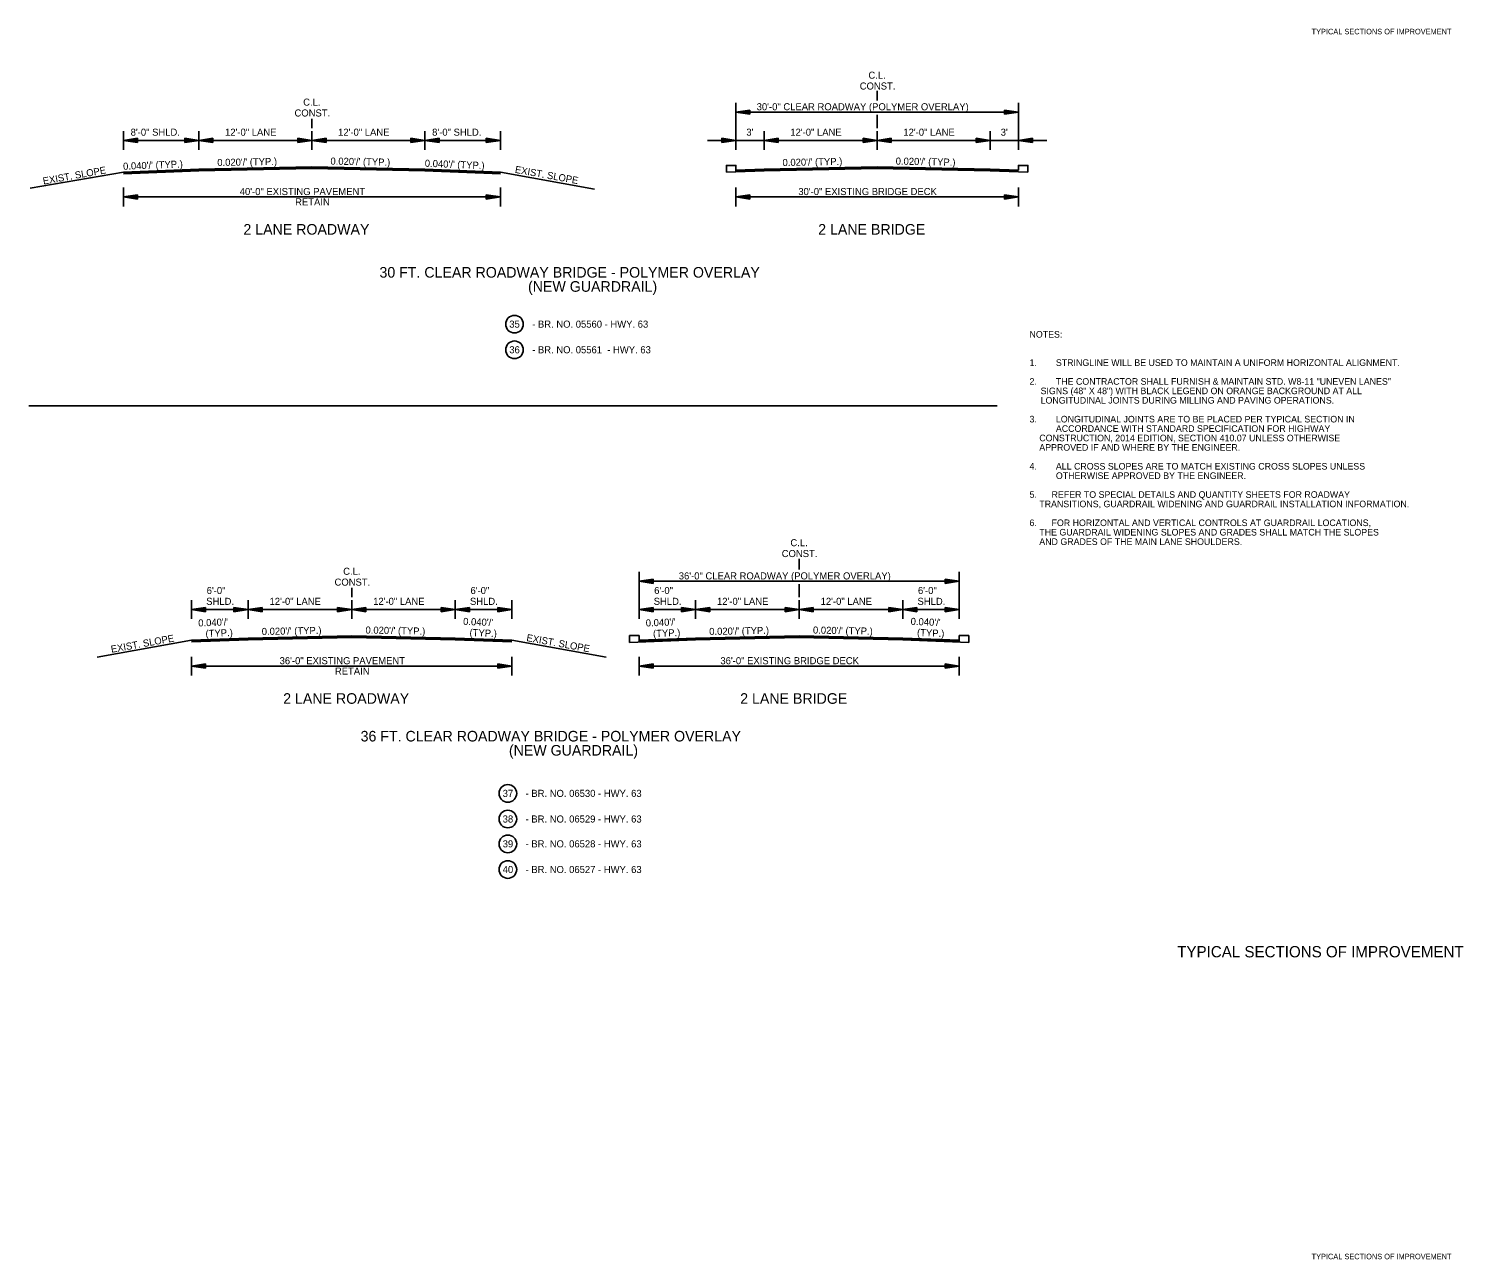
# Model space of a CAD drawing. Extents: x 545241 to 1930787, y -1971772 to 596640.
# Drawn here: x 546745 to 548268, y -1965592 to -1964286 of the extents above; entities that cross this region are included whole.
import ezdxf

# ---------------------------------------------------------------- set-up
doc = ezdxf.new("R2010")
doc.units = 0
for name, color, linetype in [('R_Border', 7, 'Continuous'), ('R_Border Notes', 7, 'Continuous'), ('R_Border Prem', 7, 'Continuous'), ('R_Draft', 7, 'Continuous')]:
    doc.layers.add(name, color=color, linetype=linetype)

# ---------------------------------------------------------------- blocks, each defined once
blk = doc.blocks.new('ARROW')
at = {"layer": 'R_Draft'}
for p, q in [((-2, 0.3), (0, 0)), ((-2, 0.3), (-2, -0.3)), ((-2, 0.25), (-0.334, 0)), ((-2, 0.199), (-0.678, 0)), ((-2, 0.149), (-1.011, 0)), ((-2, 0.097), (-1.35, 0)), ((-2, 0.047), (-1.684, 0)), ((-2, -0.3), (0, 0)), ((-2, -0.098), (-1.35, 0)), ((-2, -0.199), (-0.678, 0)), ((-2, -0.25), (-0.334, 0)), ((-2, -0.149), (-1.011, 0)), ((-2, -0.047), (-1.684, 0))]:
    blk.add_line(p, q, dxfattribs=at)

msp = doc.modelspace()

# ---------------------------------------------------------------- linework, layer by layer
at = {"layer": 'R_Border'}
for p, q in [((547645.7, -1964352.1), (547645.7, -1964362.1)), ((547495.7, -1964364.6), (547495.7, -1964414.6)), ((547795.7, -1964364.6), (547795.7, -1964414.6)), ((547045.7, -1964381.6), (547045.7, -1964391.6)), ((547495.7, -1964374.6), (547795.7, -1964374.6)), ((547645.7, -1964377.6), (547645.7, -1964391.6)), ((546845.7, -1964394.6), (546845.7, -1964414.6)), ((546925.7, -1964394.6), (546925.7, -1964414.6)), ((547045.7, -1964394.6), (547045.7, -1964414.6)), ((547165.7, -1964394.6), (547165.7, -1964414.6)), ((547245.7, -1964394.6), (547245.7, -1964414.6)), ((547525.7, -1964394.6), (547525.7, -1964414.6)), ((547645.7, -1964394.6), (547645.7, -1964414.6)), ((547765.7, -1964394.6), (547765.7, -1964414.6)), ((546845.7, -1964404.6), (547245.7, -1964404.6)), ((547465.7, -1964404.6), (547825.7, -1964404.6)), ((546845.7, -1964438.2), (546746.5, -1964455.3)), ((547245.7, -1964438.2), (547345.7, -1964456.2)), ((546845.7, -1964454.6), (546845.7, -1964474.6)), ((547245.7, -1964454.6), (547245.7, -1964474.6)), ((547495.7, -1964454.6), (547495.7, -1964474.6)), ((547795.7, -1964454.6), (547795.7, -1964474.6)), ((546845.7, -1964464.6), (547245.7, -1964464.6)), ((547495.7, -1964464.6), (547795.7, -1964464.6)), ((546745.1, -1964686.1), (547773, -1964686.1)), ((547562.9, -1964848.8), (547562.9, -1964860)), ((547392.9, -1964862.5), (547392.9, -1964912.5)), ((547392.9, -1964872.5), (547732.9, -1964872.5)), ((547732.9, -1964862.5), (547732.9, -1964912.5)), ((547087.9, -1964879.5), (547087.9, -1964889.5)), ((547562.9, -1964875.5), (547562.9, -1964889.5)), ((546917.9, -1964892.5), (546917.9, -1964912.5)), ((546917.9, -1964902.5), (547257.9, -1964902.5)), ((546977.9, -1964892.5), (546977.9, -1964912.5)), ((547087.9, -1964892.5), (547087.9, -1964912.5)), ((547197.9, -1964892.5), (547197.9, -1964912.5)), ((547257.9, -1964892.5), (547257.9, -1964912.5)), ((547392.9, -1964902.5), (547732.9, -1964902.5)), ((547452.9, -1964892.5), (547452.9, -1964912.5)), ((547562.9, -1964892.5), (547562.9, -1964912.5)), ((547672.9, -1964892.5), (547672.9, -1964912.5)), ((546917.9, -1964935.1), (546817.9, -1964953.1)), ((547257.9, -1964935.1), (547357.9, -1964953.1)), ((546917.9, -1964952.5), (546917.9, -1964972.5)), ((546917.9, -1964962.5), (547257.9, -1964962.5)), ((547257.9, -1964952.5), (547257.9, -1964972.5)), ((547392.9, -1964952.5), (547392.9, -1964972.5)), ((547392.9, -1964962.5), (547732.9, -1964962.5)), ((547732.9, -1964952.5), (547732.9, -1964972.5))]:
    msp.add_line(p, q, dxfattribs=at)
for points in [[(547495.7, -1964437.7), (547495.7, -1964431.2), (547485.7, -1964431.2), (547485.7, -1964438.4)], [(547795.7, -1964436.2), (547795.7, -1964431.2), (547805.7, -1964431.2), (547805.7, -1964438.4)], [(546845.7, -1964438.2), (546925.7, -1964435), (547045.7, -1964432.6), (547165.7, -1964435), (547245.7, -1964438.2)], [(546845.7, -1964438.5), (546925.7, -1964435.3), (547045.7, -1964432.9), (547165.7, -1964435.3), (547245.7, -1964438.5)], [(546845.7, -1964438.8), (546925.7, -1964435.6), (547045.7, -1964433.2), (547165.7, -1964435.6), (547245.7, -1964438.8)], [(546845.7, -1964439.1), (546925.7, -1964435.9), (547045.7, -1964433.5), (547165.7, -1964435.9), (547245.7, -1964439.1)], [(546845.7, -1964439.4), (546925.7, -1964436.2), (547045.7, -1964433.8), (547165.7, -1964436.2), (547245.7, -1964439.4)], [(546845.7, -1964439.7), (546925.7, -1964436.5), (547045.7, -1964434.1), (547165.7, -1964436.5), (547245.7, -1964439.7)], [(546845.7, -1964440), (546925.7, -1964436.8), (547045.7, -1964434.4), (547165.7, -1964436.8), (547245.7, -1964440)], [(547485.7, -1964438.4), (547525.7, -1964436.8), (547645.7, -1964434.4), (547765.7, -1964436.8), (547805.7, -1964438.4)], [(547495.7, -1964436.2), (547525.7, -1964435), (547645.7, -1964432.6), (547765.7, -1964435), (547795.7, -1964436.2)], [(547495.7, -1964436.5), (547525.7, -1964435.3), (547645.7, -1964432.9), (547765.7, -1964435.3), (547795.7, -1964436.5)], [(547495.7, -1964436.8), (547525.7, -1964435.6), (547645.7, -1964433.2), (547765.7, -1964435.6), (547795.7, -1964436.8)], [(547495.7, -1964437.1), (547525.7, -1964435.9), (547645.7, -1964433.5), (547765.7, -1964435.9), (547795.7, -1964437.1)], [(547495.7, -1964437.4), (547525.7, -1964436.2), (547645.7, -1964433.8), (547765.7, -1964436.2), (547795.7, -1964437.4)], [(547495.7, -1964437.7), (547525.7, -1964436.5), (547645.7, -1964434.1), (547765.7, -1964436.5), (547795.7, -1964437.7)], [(546917.9, -1964935.1), (546977.9, -1964932.7), (547087.9, -1964930.5), (547197.9, -1964932.7), (547257.9, -1964935.1)], [(546917.9, -1964935.4), (546977.9, -1964933), (547087.9, -1964930.8), (547197.9, -1964933), (547257.9, -1964935.4)], [(546917.9, -1964935.7), (546977.9, -1964933.3), (547087.9, -1964931.1), (547197.9, -1964933.3), (547257.9, -1964935.7)], [(546917.9, -1964936), (546977.9, -1964933.6), (547087.9, -1964931.4), (547197.9, -1964933.6), (547257.9, -1964936)], [(546917.9, -1964936.3), (546977.9, -1964933.9), (547087.9, -1964931.7), (547197.9, -1964933.9), (547257.9, -1964936.3)], [(546917.9, -1964936.6), (546977.9, -1964934.2), (547087.9, -1964932), (547197.9, -1964934.2), (547257.9, -1964936.6)], [(546917.9, -1964936.9), (546977.9, -1964934.5), (547087.9, -1964932.3), (547197.9, -1964934.5), (547257.9, -1964936.9)], [(547392.9, -1964936.6), (547392.9, -1964930.1), (547382.9, -1964930.1), (547382.9, -1964937.3)], [(547382.9, -1964937.3), (547452.9, -1964934.5), (547562.9, -1964932.3), (547672.9, -1964934.5), (547742.9, -1964937.3)], [(547392.9, -1964935.1), (547452.9, -1964932.7), (547562.9, -1964930.5), (547672.9, -1964932.7), (547732.9, -1964935.1)], [(547392.9, -1964935.4), (547452.9, -1964933), (547562.9, -1964930.8), (547672.9, -1964933), (547732.9, -1964935.4)], [(547392.9, -1964935.7), (547452.9, -1964933.3), (547562.9, -1964931.1), (547672.9, -1964933.3), (547732.9, -1964935.7)], [(547392.9, -1964936), (547452.9, -1964933.6), (547562.9, -1964931.4), (547672.9, -1964933.6), (547732.9, -1964936)], [(547392.9, -1964936.3), (547452.9, -1964933.9), (547562.9, -1964931.7), (547672.9, -1964933.9), (547732.9, -1964936.3)], [(547392.9, -1964936.6), (547452.9, -1964934.2), (547562.9, -1964932), (547672.9, -1964934.2), (547732.9, -1964936.6)], [(547732.9, -1964937.3), (547732.9, -1964930.1), (547742.9, -1964930.1), (547742.9, -1964937.3)]]:
    msp.add_lwpolyline(points, dxfattribs=at)
for centre in [(547260.7, -1964599.6), (547260.7, -1964626.8), (547253.7, -1965097.6), (547253.7, -1965124.8), (547253.7, -1965151.2), (547253.7, -1965178.4)]:
    msp.add_circle(centre, 9.34, dxfattribs=at)

# ---------------------------------------------------------------- block references
at = {"layer": 'R_Border', "xscale": 7.5, "yscale": 7.5, "rotation": 180}
for p in [(547495.7, -1964374.6), (546845.7, -1964404.6), (546925.7, -1964404.6), (547045.7, -1964404.6), (547165.7, -1964404.6), (547525.7, -1964404.6), (547645.7, -1964404.6), (547795.7, -1964404.6), (546845.7, -1964464.6), (547495.7, -1964464.6), (547392.9, -1964872.5), (546917.9, -1964902.5), (546977.9, -1964902.5), (547087.9, -1964902.5), (547197.9, -1964902.5), (547392.9, -1964902.5), (547452.9, -1964902.5), (547562.9, -1964902.5), (547672.9, -1964902.5), (546917.9, -1964962.5), (547392.9, -1964962.5)]:
    msp.add_blockref('ARROW', p, dxfattribs=at)
at = {"layer": 'R_Border', "xscale": 7.5, "yscale": 7.5}
for p in [(547795.7, -1964374.6), (546925.7, -1964404.6), (547045.7, -1964404.6), (547165.7, -1964404.6), (547245.7, -1964404.6), (547495.7, -1964404.6), (547645.7, -1964404.6), (547765.7, -1964404.6), (547245.7, -1964464.6), (547795.7, -1964464.6), (547732.9, -1964872.5), (546977.9, -1964902.5), (547087.9, -1964902.5), (547197.9, -1964902.5), (547257.9, -1964902.5), (547452.9, -1964902.5), (547562.9, -1964902.5), (547672.9, -1964902.5), (547732.9, -1964902.5), (547257.9, -1964962.5), (547732.9, -1964962.5)]:
    msp.add_blockref('ARROW', p, dxfattribs=at)

# ---------------------------------------------------------------- texts
at = {"layer": 'R_Border'}
for s, height, p in [('C.L.', 7.5, (547636.4, -1964339.1)), ('CONST.', 7.5, (547627.2, -1964350.6)), ('C.L.', 7.5, (547036.4, -1964367.7)), ('30\'-0" CLEAR ROADWAY (POLYMER OVERLAY)', 7.5, (547517.8, -1964372.6)), ('CONST.', 7.5, (547027.2, -1964379.2)), ('8\'-0" SHLD.', 7.5, (546853.3, -1964399.6)), ('12\'-0" LANE', 7.5, (546953.5, -1964399.6)), ('12\'-0" LANE', 7.5, (547073.5, -1964399.6)), ('8\'-0" SHLD.', 7.5, (547173.3, -1964399.6)), ("3'", 7.5, (547506.8, -1964399.6)), ('12\'-0" LANE', 7.5, (547553.5, -1964399.6)), ('12\'-0" LANE', 7.5, (547673.5, -1964399.6)), ("3'", 7.5, (547776.8, -1964399.6)), ('40\'-0" EXISTING PAVEMENT', 7.5, (546969.1, -1964462.6)), ('30\'-0" EXISTING BRIDGE DECK', 7.5, (547562, -1964462.6)), ('RETAIN', 7.5, (547027.9, -1964473.6)), ('2 LANE ROADWAY', 11.25, (546973, -1964504.6)), ('2 LANE BRIDGE', 11.25, (547583.1, -1964504.6)), ('30 FT. CLEAR ROADWAY BRIDGE - POLYMER OVERLAY', 11.25, (547117.4, -1964550.2)), ('(NEW GUARDRAIL)', 11.25, (547275.1, -1964565.2)), ('C.L.', 7.5, (547553.6, -1964835.3)), ('CONST.', 7.5, (547544.4, -1964846.8)), ('C.L.', 7.5, (547078.9, -1964865.6)), ('CONST.', 7.5, (547069.7, -1964877.1)), ('36\'-0" CLEAR ROADWAY (POLYMER OVERLAY)', 7.5, (547435.1, -1964870.5)), ('6\'-0"', 7.5, (546934, -1964886)), ('6\'-0"', 7.5, (547214, -1964886)), ('6\'-0"', 7.5, (547409, -1964886)), ('6\'-0"', 7.5, (547689, -1964886)), ('SHLD.', 7.5, (546933.5, -1964897.5)), ('12\'-0" LANE', 7.5, (547000.7, -1964897.5)), ('12\'-0" LANE', 7.5, (547110.7, -1964897.5)), ('SHLD.', 7.5, (547213.5, -1964897.5)), ('SHLD.', 7.5, (547408.5, -1964897.5)), ('12\'-0" LANE', 7.5, (547475.7, -1964897.5)), ('12\'-0" LANE', 7.5, (547585.7, -1964897.5)), ('SHLD.', 7.5, (547688.5, -1964897.5)), ('36\'-0" EXISTING PAVEMENT', 7.5, (547011.4, -1964960.5)), ('RETAIN', 7.5, (547070.1, -1964971.5)), ('36\'-0" EXISTING BRIDGE DECK', 7.5, (547479.3, -1964960.5)), ('2 LANE ROADWAY', 11.25, (547015.2, -1965002.5)), ('2 LANE BRIDGE', 11.25, (547500.3, -1965002.5)), ('36 FT. CLEAR ROADWAY BRIDGE - POLYMER OVERLAY', 11.25, (547097.4, -1965042.5)), ('(NEW GUARDRAIL)', 11.25, (547254.8, -1965057.5))]:
    msp.add_text(s, height=height, dxfattribs=at).set_placement(p)
for s, height, rotation, p in [("0.040'/' (TYP.)", 7.5, 2.2916, (546845.4, -1964435.8)), ("0.020'/' (TYP.)", 7.5, 1.1458, (546945.3, -1964431.8)), ("0.020'/' (TYP.)", 7.5, 358.8542, (547065.3, -1964430.2)), ("0.040'/' (TYP.)", 7.5, 357.7084, (547165.4, -1964432.5)), ('EXIST. SLOPE', 7.5, 349.796, (547260.8, -1964438.9)), ("0.020'/' (TYP.)", 7.5, 1.1458, (547545.3, -1964431.8)), ("0.020'/' (TYP.)", 7.5, 358.8542, (547665.3, -1964430.2)), ('EXIST. SLOPE', 7.5, 10.204, (546760.8, -1964451.5)), ("0.040'/'", 7.5, 2.2916, (546925.2, -1964920.5)), ("0.040'/'", 7.5, 357.7084, (547206.1, -1964918.7)), ("0.040'/'", 7.5, 2.2916, (547400.2, -1964920.5)), ("0.040'/'", 7.5, 357.7084, (547681.1, -1964918.7)), ('EXIST. SLOPE', 7.5, 10.204, (546833, -1964948.4)), ('(TYP.)', 7.5, 2.2916, (546932.9, -1964931.7)), ("0.020'/' (TYP.)", 7.5, 1.1458, (546992.5, -1964929.5)), ("0.020'/' (TYP.)", 7.5, 358.8542, (547102.5, -1964927.9)), ('(TYP.)', 7.5, 357.7084, (547212.9, -1964930.5)), ('EXIST. SLOPE', 7.5, 349.796, (547273, -1964935.8)), ('(TYP.)', 7.5, 2.2916, (547407.9, -1964931.7)), ("0.020'/' (TYP.)", 7.5, 1.1458, (547467.5, -1964929.5)), ("0.020'/' (TYP.)", 7.5, 358.8542, (547577.5, -1964927.9)), ('(TYP.)', 7.5, 357.7084, (547687.9, -1964930.5)), ('TYPICAL SECTIONS OF IMPROVEMENT', 12, 360, (547964.2, -1965271.6))]:
    msp.add_text(s, height=height, rotation=rotation, dxfattribs=at).set_placement(p)
at = {"layer": 'R_Border Notes'}
for s, p in [('NOTES: ', (547807.4, -1964613.9)), ('1.', (547807.4, -1964643.9)), ('STRINGLINE WILL BE USED TO MAINTAIN A UNIFORM HORIZONTAL ALIGNMENT.', (547835.4, -1964643.9)), ('2.', (547807.4, -1964663.9)), ('THE CONTRACTOR SHALL FURNISH & MAINTAIN STD. W8-11 "UNEVEN LANES" ', (547835.4, -1964663.9)), ('    SIGNS (48" X 48") WITH BLACK LEGEND ON ORANGE BACKGROUND AT ALL ', (547808.8, -1964673.9)), ('    LONGITUDINAL JOINTS DURING MILLING AND PAVING OPERATIONS.', (547808.8, -1964683.9)), ('3.', (547807.4, -1964703.9)), ('LONGITUDINAL JOINTS ARE TO BE PLACED PER TYPICAL SECTION IN ', (547835.4, -1964703.9)), ('    CONSTRUCTION, 2014 EDITION, SECTION 410.07 UNLESS OTHERWISE', (547807.4, -1964723.9)), ('ACCORDANCE WITH STANDARD SPECIFICATION FOR HIGHWAY', (547835.4, -1964713.9)), ('    APPROVED IF AND WHERE BY THE ENGINEER.', (547807.4, -1964733.9)), ('4.', (547807.4, -1964753.9)), ('ALL CROSS SLOPES ARE TO MATCH EXISTING CROSS SLOPES UNLESS ', (547835.4, -1964753.9)), ('OTHERWISE APPROVED BY THE ENGINEER.', (547835.4, -1964763.9)), ('5.      REFER TO SPECIAL DETAILS AND QUANTITY SHEETS FOR ROADWAY', (547807.4, -1964783.9)), ('    TRANSITIONS, GUARDRAIL WIDENING AND GUARDRAIL INSTALLATION INFORMATION.', (547807.4, -1964793.9)), ('6.      FOR HORIZONTAL AND VERTICAL CONTROLS AT GUARDRAIL LOCATIONS,', (547807.4, -1964813.9)), ('    AND GRADES OF THE MAIN LANE SHOULDERS.  ', (547807.4, -1964833.9)), ('    THE GUARDRAIL WIDENING SLOPES AND GRADES SHALL MATCH THE SLOPES', (547807.4, -1964823.9))]:
    msp.add_text(s, height=7, dxfattribs=at).set_placement(p)
at = {"layer": 'R_Border Prem'}
for p in [(548106.8, -1964292), (548106.8, -1965592)]:
    msp.add_text('TYPICAL SECTIONS OF IMPROVEMENT', height=5.862, rotation=360, dxfattribs=at).set_placement(p)
at = {"layer": 'R_Draft'}
for s, p in [('35', (547255.2, -1964603.3)), ('- BR. NO. 05560 - HWY. 63', (547279.5, -1964603.3)), ('36', (547255.2, -1964630.5)), ('- BR. NO. 05561  - HWY. 63', (547279.5, -1964630.5)), ('37', (547248.2, -1965101.3)), ('- BR. NO. 06530 - HWY. 63', (547272.5, -1965101.3)), ('38', (547248.2, -1965128.5)), ('- BR. NO. 06529 - HWY. 63', (547272.5, -1965128.5)), ('39', (547248.2, -1965154.9)), ('- BR. NO. 06528 - HWY. 63', (547272.5, -1965154.9)), ('40', (547248.2, -1965182.1)), ('- BR. NO. 06527 - HWY. 63', (547272.5, -1965182.1))]:
    msp.add_text(s, height=7.5, dxfattribs=at).set_placement(p)

doc.saveas('drawing.dxf')
